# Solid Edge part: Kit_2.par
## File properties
Author: ahadarics
Last saved by: ahadarics
Revision: 76
Sűrűség: 0,000 kg/m^3
Pontosság: 0,990
Username: ahadarics
Dokumentum tartalom típus: 0
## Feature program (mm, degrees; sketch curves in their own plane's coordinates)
base feature "unnamed BaseFeature 1"
sketch for "unnamed Protrusion 1" #1 plane through (0, 30.75, 0) normal (0, 1, 0) x-axis (0, 0, -1)
  line (-7.5498, -8) -> (7.5498, -8)
  arc centre (0, 0) radius 11 from (7.5498, -8) to (-7.5498, -8) cw
sketch for "unnamed Protrusion 1" #2 plane through (0, 30.75, 0) normal (0, 1, 0) x-axis (0, 0, -1)
  line (-7.5498, 8) -> (7.5498, 8)
extrude "unnamed Protrusion 1" add to key point along -normal
thread "unnamed Thread 1"
chamfer "unnamed Chamfer 1"
sketch for "Kivágás_1" #1 plane through (0, 30.75, 0) normal (0, 1, 0) x-axis (0, 0, -1)
  line (-7.5498, 8) -> (7.5498, 8)
sketch for "Kivágás_1" #2 plane through (0, 30.75, 0) normal (0, 1, 0) x-axis (0, 0, -1)
  line (-7.5498, -8) -> (7.5498, -8)
  arc centre (0, 0) radius 11 from (7.5498, -8) to (-7.5498, -8) cw
extrude "Kivágás_1" cut finite 18 along -normal
sketch for "Furat_1" plane through (0, 3, 12) normal (0, 0, 1) x-axis (0, 1, 0)
  hole centre (-0.25, 0) bore radius 4.283
hole "Furat_1" nominal diameter 9.728 finite  ThreadDepth = 7.5 mm
chamfer "Letörés_2" setback 0.7
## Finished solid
Body 1: solid body, 32 faces, 71 edges, 40 vertices.
  Faces by surface: plane 13, cylinder 11, cone 8
  Edges by curve: line 32, circle 31, intersection 4, spline 4
Bounding box of the edges (mm): 27.000 x 37.500 x 25.500, from (-13.5, -6.75, -13.5) to (13.5, 30.75, 12).
Cylindrical faces by radius (mm): R4 x1, R4.28 x1, R4.283 x1, R9.85 x2, R11 x4, R11.1 x1, R13.5 x1
Conical faces (half-angle, radius in mm at the cone's reference point): 45 deg R4.1 x2, 45 deg R4.983 x1, 45 deg R11 x2, 59 deg R2.1415 x1, 60 deg R10.425 x2
Planar faces by outward normal: +x 1, +y 7, +z 2, -x 1, -y 2
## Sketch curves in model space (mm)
arc centre (0, 30.75, 0) radius 11 from (8, 30.75, -7.5498) through (11, 30.75, 0) to (8, 30.75, 7.5498)
line (8, 30.75, 7.5498) -> (8, 30.75, -7.5498)
arc centre (0, 30.75, 0) radius 11 from (-8, 30.75, 7.5498) through (-11, 30.75, 0) to (-8, 30.75, -7.5498)
line (-8, 30.75, 7.5498) -> (-8, 30.75, -7.5498)
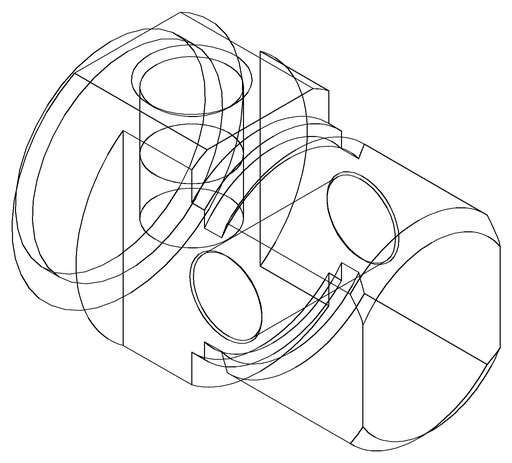
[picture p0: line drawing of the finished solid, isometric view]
